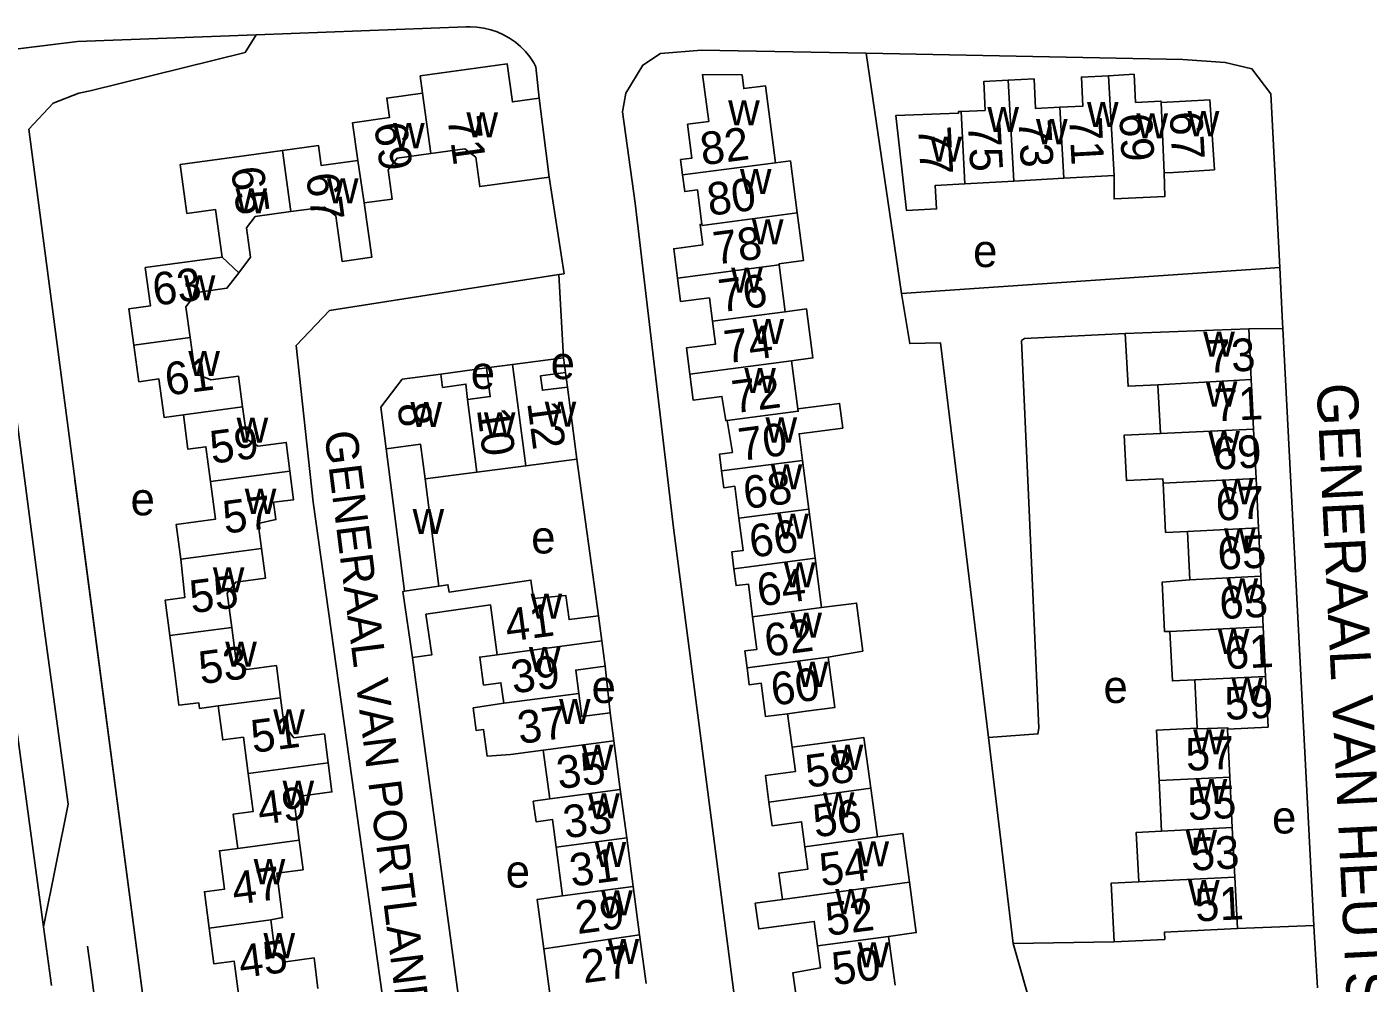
# Model space of a CAD drawing. Extents: x 159294 to 161936, y 384538 to 386517.
# Drawn here: x 161160.6 to 161324.8, y 386038.1 to 386155.2 of the extents above; entities that cross this region are included whole.
import ezdxf

# ---------------------------------------------------------------- set-up
doc = ezdxf.new("R2010")
doc.units = 0
for name, color, linetype in [('BLT_Basislijn', 7, 'Continuous'), ('BLT_Bebouwing', 7, 'Continuous'), ('BLT_Centroide', 7, 'Continuous'), ('BLT_Huisnummer', 7, 'Continuous'), ('BLT_Huisnummer_ tussenligend', 7, 'Continuous'), ('BLT_Onderverdeling_panden', 7, 'Continuous'), ('BLT_Straatnaam', 7, 'Continuous'), ('BLT_Straatnaam_verkleind', 7, 'Continuous')]:
    doc.layers.add(name, color=color, linetype=linetype)

msp = doc.modelspace()

# ---------------------------------------------------------------- linework, layer by layer
at = {"layer": 'BLT_Basislijn'}
for p, q in [((161188.68, 386154.18), (161214.35, 386155.15)), ((161166.79, 386153.36), (161188.68, 386154.18)), ((161267.67, 386122.52), (161263.34, 386151.92)), ((161222.91, 386150.28), (161223.3, 386146.42)), ((161154.81, 386141.85), (161162.59, 386082.43)), ((161180.14, 385996.06), (161160.82, 386142.62)), ((161162.65, 386045), (161149.54, 386141.23)), ((161224.54, 386136.77), (161226.35, 386124.94)), ((161226.35, 386124.94), (161225.7, 386124.84)), ((161313.96, 386125.69), (161267.67, 386122.52)), ((161225.7, 386124.84), (161226.3, 386114.65)), ((161314.32, 386118.25), (161310.17, 386118.19)), ((161318.14, 386045.16), (161314.32, 386118.25)), ((161226.3, 386114.65), (161226.54, 386112.84)), ((161211.28, 386112.65), (161216.86, 386113.43)), ((161226.54, 386112.84), (161226.76, 386111.08)), ((161227.91, 386102.25), (161230.56, 386083.09)), ((161180.14, 385996.06), (161166.48, 386099.66)), ((161231.38, 386076.91), (161231.98, 386071.21)), ((161253.71, 386071.09), (161254.28, 386066.99)), ((161281.34, 386042.98), (161278.29, 386068.18)), ((161162.65, 386045), (161165.65, 386060.02)), ((161163.63, 386037.83), (161162.65, 386045)), ((161308.77, 386044.8), (161318.14, 386045.16)), ((161281.34, 386042.98), (161293.68, 386043.18)), ((161186.66, 385903.12), (161168.58, 386038.51))]:
    msp.add_line(p, q, dxfattribs=at)
for points in [[(161222.91, 386150.28), (161222.65, 386150.76), (161222.18, 386151.47), (161221.64, 386152.13), (161221.04, 386152.74), (161220.39, 386153.29), (161219.69, 386153.77), (161218.95, 386154.19), (161218.17, 386154.54), (161217.37, 386154.81), (161216.54, 386155.01), (161215.69, 386155.12), (161214.84, 386155.16), (161214.35, 386155.15)], [(161153.52, 386151.74), (161166.79, 386153.36), (161188.68, 386154.18)], [(161168.36, 386147.33), (161187.33, 386152.02), (161188.68, 386154.18)], [(161263.34, 386151.92), (161243.16, 386152.29), (161238.17, 386151.9), (161236, 386150.47), (161233.91, 386147.05), (161233.5, 386144.74), (161235.07, 386133.58), (161239.76, 386093.85), (161255.12, 385975.42)], [(161263.34, 386151.92), (161302.09, 386151.17), (161307.29, 386150.8), (161310.54, 386150.04), (161312.85, 386146.97), (161313.96, 386125.69)], [(161168.36, 386147.33), (161166.95, 386147.03), (161163.83, 386145.83), (161160.82, 386142.62)], [(161314.32, 386118.25), (161314.29, 386118.91), (161313.96, 386125.69)], [(161225.7, 386124.84), (161197.66, 386120.44), (161193.58, 386116.17), (161195.65, 386096.98), (161206.96, 386016.4), (161200.01, 385999.01), (161199.55, 385998.5)], [(161278.29, 386068.18), (161272.43, 386116.48), (161268.66, 386116.39), (161267.67, 386122.52)], [(161295.05, 386117.61), (161282.73, 386117.03), (161282.35, 386116.76), (161283.21, 386097.83)], [(161283.21, 386097.83), (161284.48, 386069.34), (161284.35, 386068.62), (161278.29, 386068.18)], [(161165.65, 386060.02), (161162.59, 386082.43)], [(161207.81, 386077.97), (161215.89, 386018.38), (161216.09, 386016.63)], [(161318.56, 386037.56), (161318.18, 386044.4), (161318.14, 386045.16)], [(161287.43, 386001.85), (161286.04, 386026.38), (161281.34, 386042.98)], [(161168.58, 386038.51), (161168.02, 386042.65)]]:
    msp.add_lwpolyline(points, dxfattribs=at)
at = {"layer": 'BLT_Bebouwing'}
for p, q in [((161223.3, 386146.42), (161224.54, 386136.77)), ((161191.89, 386140.03), (161187.48, 386139.43)), ((161287.54, 386136.62), (161281.4, 386136.28)), ((161293.68, 386136.95), (161287.54, 386136.62)), ((161281.4, 386136.28), (161275.42, 386135.95)), ((161183.7, 386132.8), (161184.49, 386126.98)), ((161252.68, 386126.02), (161253.42, 386120.29)), ((161310.17, 386118.19), (161295.05, 386117.61)), ((161310.47, 386111.99), (161310.17, 386118.19)), ((161216.86, 386113.43), (161220.05, 386113.84)), ((161220.05, 386113.84), (161226.3, 386114.65)), ((161254.2, 386114.3), (161254.97, 386108.39)), ((161310.76, 386105.94), (161310.47, 386111.99)), ((161226.76, 386111.08), (161227.91, 386102.25)), ((161299.34, 386105.39), (161299.02, 386111.36)), ((161311.05, 386099.88), (161310.76, 386105.94)), ((161204.57, 386103.53), (161206.84, 386086.1)), ((161227.91, 386102.25), (161221.66, 386101.44)), ((161255.53, 386102.1), (161256.31, 386096.13)), ((161215.68, 386100.66), (161209.34, 386099.84)), ((161221.66, 386101.44), (161215.68, 386100.66)), ((161209.34, 386099.84), (161211.04, 386086.72)), ((161311.34, 386093.83), (161311.05, 386099.88)), ((161256.31, 386096.13), (161257.09, 386090.15)), ((161311.63, 386087.91), (161311.34, 386093.83)), ((161302.95, 386087.48), (161302.65, 386093.41)), ((161257.09, 386090.15), (161257.88, 386084.08)), ((161311.93, 386081.72), (161311.63, 386087.91)), ((161230.97, 386080), (161230.56, 386083.09)), ((161312.22, 386075.67), (161311.93, 386081.72)), ((161231.38, 386076.91), (161230.97, 386080)), ((161303.85, 386069.33), (161303.55, 386075.25)), ((161232.44, 386067.77), (161231.98, 386071.21)), ((161307.85, 386063.33), (161307.56, 386069.22)), ((161233.23, 386061.84), (161232.44, 386067.77)), ((161223.8, 386066.62), (161224.59, 386060.68)), ((161299.48, 386056.73), (161299.18, 386062.91)), ((161308.15, 386057.16), (161307.85, 386063.33)), ((161234.02, 386055.9), (161233.23, 386061.84)), ((161264.7, 386056.02), (161263.9, 386061.98)), ((161308.45, 386051.1), (161308.15, 386057.16)), ((161225.38, 386054.75), (161226.17, 386048.81)), ((161234.81, 386049.96), (161234.02, 386055.9)), ((161308.77, 386044.8), (161308.45, 386051.1)), ((161235.6, 386044.03), (161234.81, 386049.96)), ((161236.39, 386038.09), (161235.6, 386044.03)), ((161266.87, 386037.89), (161266.06, 386043.84))]:
    msp.add_line(p, q, dxfattribs=at)
for points in [[(161223.3, 386146.42), (161220.03, 386145.98), (161219.4, 386150.62), (161208.75, 386149.16), (161209.04, 386147.04)], [(161240.86, 386137.03), (161240.61, 386138.92), (161242.01, 386139.1), (161241.47, 386143.23), (161244.06, 386143.57), (161243.31, 386149.32), (161248.14, 386149.27), (161248.35, 386147.61), (161251, 386147.94), (161252.22, 386138.52)], [(161274.94, 386144.81), (161277.88, 386144.93), (161277.72, 386148.46), (161280.71, 386148.62)], [(161280.71, 386148.62), (161283.88, 386148.79), (161284.07, 386145.15), (161287.05, 386145.31)], [(161287.05, 386145.31), (161289.86, 386145.46), (161289.67, 386149.01), (161293, 386149.18)], [(161293, 386149.18), (161296.12, 386149.35), (161296.31, 386145.91), (161299.41, 386146.07), (161299.42, 386145.88)], [(161209.04, 386147.04), (161204.65, 386146.44), (161204.98, 386144.05), (161200.47, 386143.43), (161201.11, 386138.79)], [(161275.42, 386135.95), (161271.79, 386135.75), (161271.94, 386132.88), (161268.28, 386132.68), (161266.97, 386144.3), (161274.65, 386144.61), (161274.64, 386144.8), (161274.94, 386144.81)], [(161299.42, 386145.88), (161305.41, 386146.22), (161305.95, 386137.66), (161300.96, 386137.35), (161299.82, 386137.29)], [(161201.11, 386138.79), (161196.64, 386138.18), (161196.3, 386140.63), (161191.89, 386140.03)], [(161210.05, 386139.65), (161214.19, 386140.22), (161215.55, 386139.19), (161216.04, 386135.61), (161224.54, 386136.77)], [(161183.7, 386132.8), (161180.18, 386132.32), (161179.36, 386138.31), (161187.48, 386139.43)], [(161201.87, 386133.61), (161205.32, 386134.08), (161204.83, 386137.65), (161205.92, 386139.09), (161210.05, 386139.65)], [(161252.22, 386138.52), (161254.06, 386138.76), (161254.89, 386132.38)], [(161243.23, 386131.01), (161242.69, 386135.2), (161241.12, 386135), (161240.86, 386137.03)], [(161299.82, 386137.29), (161299.9, 386134.4), (161293.68, 386134.11), (161293.68, 386136.95)], [(161192.91, 386132.54), (161197.03, 386133.1), (161198.42, 386132.04), (161199.18, 386126.46), (161202.81, 386126.96), (161201.87, 386133.61)], [(161186.54, 386125.07), (161187.98, 386126.97), (161187.49, 386130.57), (161188.53, 386131.94), (161192.91, 386132.54)], [(161254.89, 386132.38), (161255.65, 386126.56), (161252.66, 386126.17), (161252.68, 386126.02)], [(161240.24, 386124.4), (161239.77, 386128.01), (161243.33, 386128.47), (161243, 386130.98), (161243.23, 386131.01)], [(161184.49, 386126.98), (161175.09, 386125.7), (161175.73, 386121.01), (161173.09, 386120.65), (161173.7, 386116.19)], [(161180.58, 386117.13), (161180.07, 386120.91), (161181.39, 386122.65), (161185.09, 386123.16), (161186.54, 386125.07)], [(161244.52, 386119.13), (161244.15, 386121.99), (161240.61, 386121.54), (161240.24, 386124.4)], [(161253.42, 386120.29), (161256.03, 386120.63), (161256.81, 386114.64), (161254.2, 386114.3)], [(161241.73, 386112.67), (161241.32, 386115.87), (161244.89, 386116.34), (161244.52, 386119.13)], [(161187.01, 386108.65), (161186.49, 386112.42), (161183.12, 386111.96), (161181.18, 386112.75), (161180.58, 386117.13)], [(161295.05, 386117.61), (161295.4, 386111.17), (161299.02, 386111.36)], [(161173.7, 386116.19), (161174.31, 386111.73), (161176.77, 386112.07), (161177.42, 386107.34), (161179.75, 386107.66)], [(161204.57, 386103.53), (161203.91, 386108.61), (161206.55, 386112.03), (161211.28, 386112.65)], [(161211.28, 386112.65), (161211.49, 386111.04), (161214.34, 386111.43), (161214.52, 386109.54)], [(161214.52, 386109.54), (161217.32, 386109.9), (161216.86, 386113.43)], [(161226.54, 386112.84), (161223.48, 386112.44), (161223.7, 386110.69), (161226.76, 386111.08)], [(161246.33, 386106.98), (161246.15, 386106.98), (161245.68, 386109.93), (161242.15, 386109.48), (161241.73, 386112.67)], [(161192.8, 386100.79), (161192.34, 386104.3), (161188.89, 386103.83), (161187.55, 386104.67), (161187.01, 386108.65)], [(161254.97, 386108.39), (161260.07, 386109.07), (161260.47, 386106.05), (161255.11, 386105.35), (161255.53, 386102.1)], [(161179.75, 386107.66), (161180.32, 386103.47), (161182.52, 386103.77), (161183.08, 386099.52)], [(161245.63, 386100.81), (161245.36, 386102.86), (161246.96, 386103.07), (161246.33, 386106.98)], [(161299.67, 386099.32), (161299.64, 386099.85), (161295.18, 386099.63), (161294.91, 386105.17), (161299.34, 386105.39)], [(161189.32, 386091.3), (161188.92, 386094.38), (161191.08, 386094.85), (161190.8, 386096.97), (161193.25, 386097.29), (161192.8, 386100.79)], [(161247.76, 386095.01), (161247.25, 386098.93), (161245.9, 386098.76), (161245.63, 386100.81)], [(161183.08, 386099.52), (161183.68, 386094.89), (161178.89, 386094.27), (161179.45, 386090.02)], [(161302.65, 386093.41), (161299.99, 386093.28), (161299.67, 386099.32)], [(161247.14, 386088.84), (161246.87, 386090.9), (161248.28, 386091.09), (161247.76, 386095.01)], [(161185.67, 386081.64), (161185.12, 386085.85), (161186.16, 386087.2), (161189.8, 386087.68), (161189.32, 386091.3)], [(161179.45, 386090.02), (161179.92, 386085.31), (161177.53, 386085), (161178.09, 386080.65)], [(161249.43, 386082.97), (161248.91, 386086.97), (161247.41, 386086.77), (161247.14, 386088.84)], [(161230.56, 386083.09), (161226.96, 386082.61), (161226.56, 386085.58), (161222.62, 386085.19), (161222.29, 386087.46), (161212.27, 386085.98), (161212.14, 386086.88), (161211.04, 386086.72)], [(161300.52, 386081.17), (161299.85, 386081.14), (161299.55, 386087.19), (161302.95, 386087.48)], [(161206.84, 386086.1), (161206.62, 386086.07), (161207.81, 386077.97)], [(161207.81, 386077.97), (161210.18, 386078.32), (161209.45, 386083.26), (161217.35, 386084.42), (161218.17, 386078.29)], [(161257.88, 386084.08), (161262.15, 386084.63), (161262.92, 386078.77), (161258.67, 386078.01)], [(161248.75, 386076.7), (161248.48, 386078.78), (161249.96, 386078.97), (161249.43, 386082.97)], [(161178.09, 386080.65), (161178.69, 386076.06), (161179.21, 386072.14), (161181.65, 386072.42), (161181.73, 386071.75), (161184.03, 386072.05)], [(161191.66, 386073.05), (161191.14, 386076.99), (161187.52, 386076.52), (161186.21, 386077.53), (161185.67, 386081.64)], [(161303.55, 386075.25), (161300.82, 386075.12), (161300.52, 386081.17)], [(161218.17, 386078.29), (161216.04, 386078.02), (161216.5, 386074.6), (161218.62, 386074.88), (161218.96, 386072.37)], [(161258.67, 386078.01), (161259.48, 386071.85), (161255.97, 386071.39), (161253.71, 386071.09)], [(161228.17, 386073.59), (161227.79, 386076.43), (161231.38, 386076.91)], [(161253.71, 386071.09), (161251.01, 386070.74), (161250.48, 386074.82), (161249.02, 386074.63), (161248.75, 386076.7)], [(161307.56, 386069.22), (161312.52, 386069.47), (161312.22, 386075.67)], [(161197.47, 386065.07), (161197.01, 386068.62), (161193.29, 386068.14), (161192.09, 386069.7), (161191.66, 386073.05)], [(161231.98, 386071.21), (161228.54, 386070.76), (161228.17, 386073.59)], [(161184.03, 386072.05), (161184.57, 386067.89), (161187.11, 386068.22), (161187.69, 386063.79)], [(161218.96, 386072.37), (161215.24, 386071.8), (161215.61, 386069.04), (161216.5, 386069.16), (161216.94, 386065.9), (161219.8, 386066.09), (161223.8, 386066.62)], [(161299.18, 386062.91), (161298.87, 386069.08), (161303.85, 386069.33)], [(161263.9, 386061.98), (161263.06, 386068.18), (161259.23, 386067.66), (161254.28, 386066.99)], [(161254.28, 386066.99), (161254.68, 386064.03), (161250.99, 386063.53), (161251.43, 386060.29)], [(161193.94, 386055.61), (161193.4, 386059.76), (161194.39, 386061.05), (161197.93, 386061.52), (161197.47, 386065.07)], [(161187.69, 386063.79), (161188.3, 386059.14), (161185.86, 386058.82), (161186.4, 386054.62)], [(161224.59, 386060.68), (161222.58, 386060.39), (161222.94, 386057.88), (161224.93, 386058.15), (161225.38, 386054.75)], [(161251.43, 386060.29), (161251.82, 386057.39), (161255.43, 386057.88), (161255.84, 386054.82)], [(161268.63, 386050.47), (161267.82, 386056.44), (161264.7, 386056.02)], [(161296.7, 386050.54), (161296.4, 386056.57), (161299.48, 386056.73)], [(161186.4, 386054.62), (161184.17, 386054.33), (161184.79, 386049.63), (161182.32, 386049.31), (161182.9, 386044.87)], [(161190.47, 386045.86), (161191.9, 386046.14), (161191.19, 386051.57), (161194.41, 386051.99), (161193.94, 386055.61)], [(161255.84, 386054.82), (161256.21, 386052.08), (161252.63, 386051.59), (161253.07, 386048.34)], [(161266.06, 386043.84), (161269.46, 386044.3), (161268.63, 386050.47)], [(161293.68, 386043.18), (161293.33, 386050.37), (161296.7, 386050.54)], [(161226.17, 386048.81), (161223.06, 386048.36), (161223.87, 386042.34)], [(161253.07, 386048.34), (161249.76, 386047.9), (161250.19, 386044.75), (161256.97, 386045.67), (161257.38, 386042.67)], [(161182.9, 386044.87), (161183.47, 386040.49), (161185.97, 386040.82), (161186.57, 386036.22), (161188.85, 386036.51)], [(161196.23, 386037.48), (161195.75, 386041.2), (161192.26, 386040.74), (161191.01, 386041.71), (161190.47, 386045.86)], [(161293.68, 386043.18), (161299.87, 386043.48), (161299.83, 386044.36), (161308.77, 386044.8)], [(161223.87, 386042.34), (161224.64, 386036.52)], [(161257.38, 386042.67), (161257.74, 386039.99), (161254.35, 386039.38), (161254.79, 386036.26)]]:
    msp.add_lwpolyline(points, dxfattribs=at)
at = {"layer": 'BLT_Onderverdeling_panden'}
for p, q in [((161281.4, 386136.28), (161280.71, 386148.62)), ((161293.68, 386136.95), (161293, 386149.18)), ((161209.04, 386147.04), (161210.05, 386139.65)), ((161275.42, 386135.95), (161274.94, 386144.81)), ((161287.54, 386136.62), (161287.05, 386145.31)), ((161299.82, 386137.29), (161299.42, 386145.88)), ((161191.89, 386140.03), (161192.91, 386132.54)), ((161201.11, 386138.79), (161201.87, 386133.61)), ((161240.86, 386137.03), (161252.22, 386138.52)), ((161186.54, 386125.07), (161184.49, 386126.98)), ((161240.24, 386124.4), (161252.68, 386126.02)), ((161253.42, 386120.29), (161244.52, 386119.13)), ((161173.7, 386116.19), (161180.58, 386117.13)), ((161220.05, 386113.84), (161221.66, 386101.44)), ((161241.73, 386112.67), (161254.2, 386114.3)), ((161299.02, 386111.36), (161310.47, 386111.99)), ((161187.01, 386108.65), (161179.75, 386107.66)), ((161214.52, 386109.54), (161215.68, 386100.66)), ((161299.34, 386105.39), (161310.76, 386105.94)), ((161245.63, 386100.81), (161255.53, 386102.1)), ((161192.8, 386100.79), (161183.08, 386099.52)), ((161299.67, 386099.32), (161311.05, 386099.88)), ((161247.76, 386095.01), (161256.31, 386096.13)), ((161302.65, 386093.41), (161311.34, 386093.83)), ((161189.32, 386091.3), (161179.45, 386090.02)), ((161247.14, 386088.84), (161257.09, 386090.15)), ((161302.95, 386087.48), (161311.63, 386087.91)), ((161211.04, 386086.72), (161206.84, 386086.1)), ((161249.43, 386082.97), (161257.88, 386084.08)), ((161185.67, 386081.64), (161178.09, 386080.65)), ((161300.52, 386081.17), (161311.93, 386081.72)), ((161230.97, 386080), (161218.17, 386078.29)), ((161248.75, 386076.7), (161258.67, 386078.01)), ((161303.55, 386075.25), (161312.22, 386075.67)), ((161191.66, 386073.05), (161184.03, 386072.05)), ((161228.17, 386073.59), (161218.96, 386072.37)), ((161232.44, 386067.77), (161223.8, 386066.62)), ((161197.47, 386065.07), (161187.69, 386063.79)), ((161299.18, 386062.91), (161307.85, 386063.33)), ((161224.59, 386060.68), (161233.23, 386061.84)), ((161251.43, 386060.29), (161263.9, 386061.98)), ((161255.84, 386054.82), (161264.7, 386056.02)), ((161299.48, 386056.73), (161308.15, 386057.16)), ((161193.94, 386055.61), (161186.4, 386054.62)), ((161225.38, 386054.75), (161234.02, 386055.9)), ((161296.7, 386050.54), (161308.45, 386051.1)), ((161226.17, 386048.81), (161234.81, 386049.96)), ((161253.07, 386048.34), (161268.63, 386050.47)), ((161190.47, 386045.86), (161182.9, 386044.87)), ((161223.87, 386042.34), (161235.6, 386044.03)), ((161257.38, 386042.67), (161266.06, 386043.84))]:
    msp.add_line(p, q, dxfattribs=at)
for points in [[(161254.89, 386132.38), (161243.25, 386130.86), (161243.23, 386131.01)], [(161246.33, 386106.98), (161255.01, 386108.11), (161254.97, 386108.39)], [(161209.34, 386099.84), (161208.79, 386104.08), (161204.57, 386103.53)], [(161303.85, 386069.33), (161303.86, 386069.23), (161307.59, 386069.38), (161307.56, 386069.22)]]:
    msp.add_lwpolyline(points, dxfattribs=at)

# ---------------------------------------------------------------- texts
at = {"layer": 'BLT_Centroide'}
for s, p in [('w', (161214.4, 386141.62)), ('w', (161246.44, 386143.09)), ('w', (161278.17, 386142.28)), ('w', (161290.36, 386142.91)), ('w', (161302.69, 386141.77)), ('w', (161205.42, 386140.31)), ('w', (161284.12, 386140.8)), ('w', (161296.41, 386141.5)), ('w', (161271.19, 386138.66)), ('w', (161197.33, 386133.56)), ('w', (161247.88, 386134.69)), ('w', (161186.14, 386132.34)), ('w', (161249.35, 386128.53)), ('e', (161276.42, 386125.76)), ('w', (161246.8, 386122.62)), ('w', (161179.81, 386121.69)), ('w', (161249.41, 386116.34)), ('w', (161304.59, 386114.78)), ('w', (161180.36, 386112.42)), ('e', (161224.71, 386112.05)), ('e', (161214.93, 386110.85)), ('w', (161248.41, 386110.34)), ('w', (161304.9, 386108.69)), ('w', (161207.55, 386106.19)), ('w', (161223.98, 386106.23)), ('w', (161186.27, 386104.25)), ('w', (161216.54, 386104.92)), ('w', (161251.01, 386104.28)), ('w', (161305.2, 386102.62)), ('w', (161251.65, 386098.56)), ('w', (161306.85, 386096.72)), ('e', (161173.29, 386095.38)), ('w', (161187.27, 386095.55)), ('w', (161207.81, 386093.09)), ('w', (161252.44, 386092.5)), ('e', (161222.33, 386090.71)), ('w', (161307.14, 386090.72)), ('w', (161183.36, 386085.94)), ('w', (161253.26, 386086.56)), ('w', (161307.44, 386084.59)), ('w', (161222.26, 386082.72)), ('w', (161254.06, 386080.41)), ('w', (161306.37, 386078.41)), ('w', (161184.88, 386076.84)), ('w', (161222.05, 386076.19)), ('w', (161254.84, 386074.38)), ('e', (161229.72, 386072.41)), ('e', (161292.38, 386072.41)), ('w', (161308.03, 386072.44)), ('w', (161225.73, 386069.84)), ('w', (161190.75, 386068.56)), ('w', (161303.36, 386066.12)), ('w', (161228.52, 386064.22)), ('w', (161259.12, 386064.22)), ('w', (161191.89, 386059.84)), ('w', (161303.66, 386060.03)), ('w', (161229.3, 386058.28)), ('w', (161258.03, 386058.41)), ('e', (161313.01, 386056.44)), ('w', (161302.42, 386053.84)), ('w', (161230.09, 386052.34)), ('w', (161262.27, 386052.41)), ('w', (161188.36, 386050.23)), ('e', (161219.21, 386049.82)), ('w', (161230.89, 386046.41)), ('w', (161259.55, 386046.56)), ('w', (161302.73, 386047.66)), ('w', (161189.56, 386041.17)), ('w', (161231.68, 386040.47)), ('w', (161262.3, 386040.06))]:
    msp.add_text(s, height=4, dxfattribs=at).set_placement(p)
at = {"layer": 'BLT_Huisnummer'}
for s, rotation, p in [('67', 273.1932, (161300.47, 386144.73)), ('71', 277.7901, (161212.06, 386144.01)), ('71', 273.1948, (161288.16, 386144.07)), ('82', 7.5068, (161243.29, 386138.2)), ('77', 273.0846, (161269.68, 386142.91)), ('67', 277.83, (161194.74, 386137.06)), ('63', 7.4418, (161176.25, 386121.01)), ('76', 7.5068, (161245.52, 386120.22)), ('73', 2.8324, (161305.12, 386112.8)), ('72', 7.5068, (161247.16, 386107.85)), ('8', 277.3943, (161205.93, 386108.96)), ('12', 277.4052, (161221.83, 386109.16)), ('59', 7.4418, (161183.26, 386101.68)), ('68', 7.5068, (161248.55, 386096.12)), ('67', 2.8324, (161306.21, 386094.71)), ('64', 7.5068, (161250.24, 386084.21)), ('55', 7.4418, (161180.78, 386083.38)), ('63', 2.8324, (161306.66, 386082.67)), ('41', 7.5901, (161219.42, 386079.9)), ('60', 7.5068, (161251.94, 386072.07)), ('59', 2.8324, (161307.31, 386070.33)), ('51', 7.4418, (161188.28, 386066.29)), ('37', 7.5901, (161220.91, 386067.38)), ('58', 7.7012, (161256.16, 386062.02)), ('55', 2.8324, (161302.77, 386058.06)), ('33', 7.5901, (161226.51, 386055.82)), ('54', 7.7005, (161257.89, 386049.97)), ('47', 7.4418, (161185.97, 386047.7)), ('51', 2.8324, (161303.68, 386045.66)), ('29', 7.5901, (161228.01, 386044.12)), ('50', 7.275, (161259.38, 386037.86))]:
    msp.add_text(s, height=4, rotation=rotation, dxfattribs=at).set_placement(p)
at = {"layer": 'BLT_Huisnummer_ tussenligend'}
for s, rotation, p in [('69', 277.83, (161203.08, 386143.24)), ('75', 273.1948, (161275.78, 386143.28)), ('73', 273.1948, (161281.96, 386143.79)), ('69', 273.1932, (161294.3, 386144.51)), ('65', 277.83, (161185.56, 386137.83)), ('80', 7.5068, (161244.13, 386132.02)), ('78', 7.5068, (161244.87, 386126.05)), ('74', 7.5068, (161246.2, 386113.97)), ('61', 7.4418, (161177.77, 386110.02)), ('71', 2.8324, (161306.02, 386106.86)), ('10', 277.3943, (161215.68, 386108.33)), ('70', 7.5068, (161247.96, 386102.02)), ('69', 2.8324, (161305.86, 386100.95)), ('57', 7.4418, (161184.84, 386093.11)), ('66', 7.5068, (161249.29, 386090.18)), ('65', 2.8324, (161306.44, 386088.7)), ('62', 7.5068, (161251.15, 386078.05)), ('61', 2.8324, (161307.33, 386076.53)), ('53', 7.4418, (161181.89, 386074.7)), ('39', 7.5901, (161220.12, 386073.56)), ('57', 2.8324, (161302.54, 386064.09)), ('35', 7.5901, (161225.71, 386061.85)), ('49', 7.4418, (161189.1, 386057.49)), ('56', 7.7005, (161257.09, 386055.94)), ('53', 2.8324, (161303.16, 386051.89)), ('31', 7.5901, (161227.3, 386049.92)), ('52', 7.275, (161258.59, 386043.9)), ('45', 7.4418, (161186.79, 386038.75)), ('27', 7.5901, (161228.76, 386038.11))]:
    msp.add_text(s, height=4, rotation=rotation, dxfattribs=at).set_placement(p)
at = {"layer": 'BLT_Straatnaam'}
msp.add_text('GENERAAL VAN HEUTSZLAAN', height=5, rotation=272.816, dxfattribs=at).set_placement((161318.46, 386111.46))
at = {"layer": 'BLT_Straatnaam_verkleind'}
msp.add_text('GENERAAL VAN PORTLANDLAAN', height=4, rotation=277.1684, dxfattribs=at).set_placement((161197, 386105.52))

doc.saveas('drawing.dxf')
